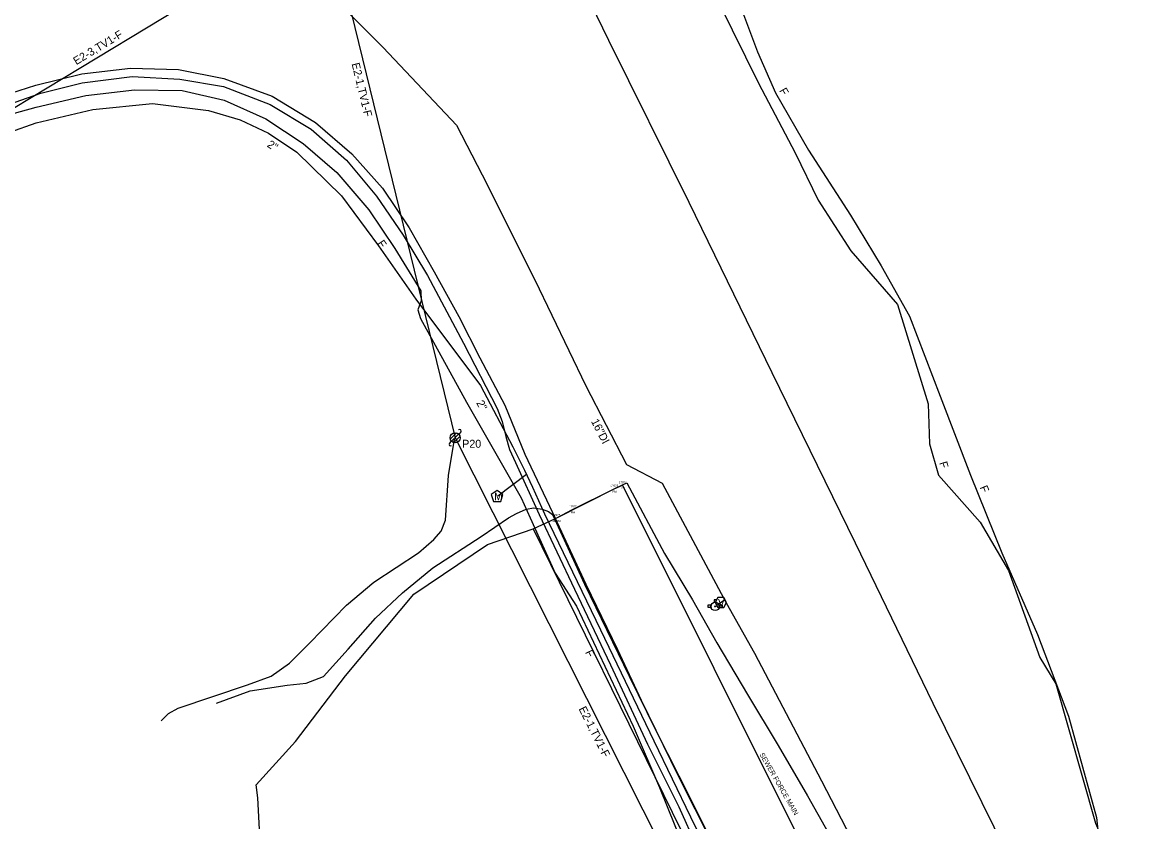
# Model space of a CAD drawing. Extents: x 1614474 to 1865144, y 1098877 to 1212550.
# Drawn here: x 1755283 to 1755840, y 1168586 to 1168985 of the extents above; entities that cross this region are included whole.
import ezdxf

# ---------------------------------------------------------------- set-up
doc = ezdxf.new("R2010")
doc.units = 0
for name, color, linetype in [('RD_EX_SU_Elec', 7, 'Continuous'), ('RD_EX_SU_H2O', 7, 'Continuous'), ('RD_EX_SU_Ovhd', 7, 'Continuous'), ('RD_EX_SU_Pole', 7, 'Continuous'), ('RD_EX_SU_Sewer', 7, 'Continuous'), ('RD_EX_SU_Telecom', 7, 'Continuous'), ('RD_EX_SU_TX_H2O', 7, 'Continuous'), ('RD_EX_SU_TX_Pole', 7, 'Continuous'), ('RD_EX_SU_TX_Sewer', 7, 'Continuous'), ('RD_EX_SU_TX_Telecom', 7, 'Continuous'), ('RD_EX_VEG_txCode', 7, 'Continuous'), ('RD_SMD_Locator', 7, 'Continuous')]:
    doc.layers.add(name, color=color, linetype=linetype)

msp = doc.modelspace()

# ---------------------------------------------------------------- linework, layer by layer
at = {"layer": 'RD_EX_SU_Elec'}
msp.add_lwpolyline([(1755352.15, 1168636.03), (1755355.71, 1168639.76), (1755360.62, 1168642.49), (1755377.96, 1168648.25), (1755395.32, 1168654.04), (1755407.08, 1168658.47), (1755416.27, 1168664.85), (1755426.19, 1168674.91), (1755444.85, 1168693.91), (1755458.49, 1168705.44), (1755480.84, 1168720.11), (1755488.48, 1168726.7), (1755492.01, 1168730.8), (1755494.34, 1168736.34), (1755495.74, 1168758.73), (1755498.75, 1168776.84)], dxfattribs=at)
at = {"layer": 'RD_EX_SU_H2O'}
for p, q in [((1755520.4, 1168748.47), (1755534.69, 1168759.32)), ((1755628.57, 1168696.63), (1755628.57, 1168695.3)), ((1755629.62, 1168696.63), (1755628.57, 1168696.63)), ((1755629.62, 1168695.27), (1755629.62, 1168696.63)), ((1755629.84, 1168693.84), (1755633.69, 1168696.62)), ((1755627.04, 1168693.86), (1755625.4, 1168693.86)), ((1755625.4, 1168693.86), (1755625.4, 1168692.81)), ((1755625.4, 1168692.81), (1755627, 1168692.81)), ((1755632.75, 1168693.86), (1755631.06, 1168693.86)), ((1755631.1, 1168692.81), (1755632.75, 1168692.81)), ((1755632.75, 1168692.81), (1755632.75, 1168693.86))]:
    msp.add_line(p, q, dxfattribs=at)
for points in [[(1755385.42, 1169098.44), (1755401.32, 1169066.46), (1755415.89, 1169036.4), (1755422.95, 1169020.76), (1755426.26, 1169009.34), (1755463.14, 1168972.48), (1755499.82, 1168933.69), (1755512.6, 1168909), (1755538.91, 1168856.4), (1755564.45, 1168803.54), (1755584.77, 1168764.26), (1755602.59, 1168754.78), (1755634.52, 1168695.09), (1755648.65, 1168669.94), (1755682.22, 1168606.15), (1755709.26, 1168554.06), (1755726.87, 1168521.3)], [(1755263.17, 1168925.56), (1755289.7, 1168934.96), (1755317.93, 1168941.55), (1755347.73, 1168944.49), (1755375.7, 1168941.09), (1755391.63, 1168936.36), (1755405.8, 1168929.69), (1755420, 1168920.26), (1755442.22, 1168898.37), (1755460.76, 1168873.49), (1755479.47, 1168846.77), (1755511.72, 1168803.69), (1755527.96, 1168773), (1755533.67, 1168761.43), (1755537.79, 1168752.87), (1755543.72, 1168739.55), (1755571.82, 1168681.62), (1755598.4, 1168626.16), (1755616.79, 1168588.07), (1755634.63, 1168551.68)]]:
    msp.add_lwpolyline(points, dxfattribs=at)
for points in [[(1755520.04, 1168751.27), (1755517.14, 1168749.16), (1755518.25, 1168745.75), (1755521.84, 1168745.75), (1755522.94, 1168749.16)], [(1755634.81, 1168695.15), (1755633.37, 1168697.65), (1755630.48, 1168697.65), (1755629.04, 1168695.15), (1755630.48, 1168692.65), (1755633.37, 1168692.65)]]:
    msp.add_lwpolyline(points, close=True, dxfattribs=at)
for radius in [2.1, 0.263]:
    msp.add_circle((1755629.05, 1168693.25), radius, dxfattribs=at)
for start, end in [(163.3387, 192.315), (74.2455, 103.2128), (347.685, 16.6613)]:
    msp.add_arc((1755629.05, 1168693.25), 2.1, start, end, dxfattribs=at)
at = {"layer": 'RD_EX_SU_Ovhd'}
for p, q in [((1755252.17, 1168926.49), (1755435.58, 1169037.63)), ((1755435.58, 1169037.63), (1755499.08, 1168777.54)), ((1755499.08, 1168777.54), (1755611.8, 1168554.19))]:
    msp.add_line(p, q, dxfattribs=at)
at = {"layer": 'RD_EX_SU_Pole'}
for p, q in [((1755496.66, 1168776.89), (1755499.72, 1168779.95)), ((1755497.31, 1168775.77), (1755500.84, 1168779.31)), ((1755500.84, 1168779.31), (1755501.9, 1168780.37)), ((1755496.25, 1168774.71), (1755497.31, 1168775.77)), ((1755498.43, 1168775.13), (1755501.49, 1168778.19))]:
    msp.add_line(p, q, dxfattribs=at)
msp.add_circle((1755499.08, 1168777.54), 2.5, dxfattribs=at)
for centre, start, end in [((1755501.37, 1168780.9), 315, 135), ((1755496.78, 1168774.18), 135, 315)]:
    msp.add_arc(centre, 0.75, start, end, dxfattribs=at)
at = {"layer": 'RD_EX_SU_Sewer'}
for points in [[(1755401.74, 1168572.3), (1755400.52, 1168597.56), (1755399.65, 1168604.04), (1755419.32, 1168625.72), (1755444.21, 1168658.58), (1755478.45, 1168699.38), (1755515.21, 1168724.24), (1755538.02, 1168731.98), (1755549.18, 1168737.18), (1755579.59, 1168752.57), (1755584.91, 1168755.1), (1755603.82, 1168719.72), (1755617.74, 1168696.64), (1755629.86, 1168675.11), (1755645.29, 1168649.26), (1755660.6, 1168623.75), (1755675.18, 1168598.54), (1755689.17, 1168573.75)], [(1755538.02, 1168731.98), (1755677.08, 1168448.83)]]:
    msp.add_lwpolyline(points, dxfattribs=at)
at = {"layer": 'RD_EX_SU_Telecom'}
for points in [[(1755590.16, 1169126.29), (1755590.98, 1169107.71), (1755588.59, 1169093.98), (1755585.74, 1169086.47), (1755598.29, 1169061.2), (1755650.69, 1168954.78), (1755669.04, 1168919.98), (1755680.52, 1168896.3), (1755696.94, 1168870.9), (1755720.15, 1168844.14), (1755735.51, 1168794.5), (1755736.19, 1168774.57), (1755740.79, 1168758.88), (1755761.5, 1168735.33), (1755775.66, 1168711.24), (1755791.36, 1168667.81), (1755799.39, 1168654.61), (1755819.15, 1168584.91), (1755822.92, 1168576.29), (1755830.76, 1168551.82), (1755839.8, 1168530.61)], [(1755515.3, 1169100.63), (1755575.8, 1168976.27), (1755615.82, 1168895.28), (1755657.46, 1168810.23), (1755699.13, 1168725.09), (1755737.87, 1168644.92), (1755774.46, 1168570.64)], [(1755643.16, 1168988.99), (1755650.24, 1168970.42), (1755659.27, 1168949.97), (1755675.7, 1168921.3), (1755696.74, 1168888.73), (1755711.98, 1168863.4), (1755726.14, 1168838.3), (1755741.49, 1168798.28), (1755756.63, 1168758.91), (1755772.29, 1168720.09), (1755790.19, 1168679.27), (1755805.71, 1168638.46), (1755819.76, 1168587.82), (1755820.42, 1168581.52)], [(1755268.41, 1168947.14), (1755289.41, 1168953.77), (1755312.39, 1168959.32), (1755336.84, 1168962.31), (1755360.73, 1168961.58), (1755383.48, 1168957.08), (1755407.65, 1168948.23), (1755429.34, 1168935), (1755447.51, 1168919.47), (1755462.71, 1168902.2), (1755476.06, 1168882.48), (1755488.57, 1168860.52), (1755500.87, 1168838.21), (1755511.35, 1168817.55), (1755523.89, 1168793.88), (1755533.94, 1168769.38), (1755547.81, 1168740.19), (1755564.48, 1168704.4), (1755580.18, 1168671.75), (1755592.08, 1168646.44), (1755610.47, 1168608.91), (1755627.34, 1168575.22)], [(1755272.39, 1168942.94), (1755291.95, 1168949.71), (1755312.56, 1168954.88), (1755337.65, 1168958.12), (1755361.46, 1168956.8), (1755383.25, 1168953.03), (1755406.57, 1168944.08), (1755427.09, 1168931.76), (1755444.74, 1168916.29), (1755459.8, 1168898.32), (1755473.09, 1168878.8), (1755485.28, 1168858.56), (1755503.24, 1168824.79), (1755520.07, 1168792.15), (1755522.53, 1168785.59), (1755524.49, 1168778.11), (1755526.21, 1168771.73), (1755529.29, 1168765.17), (1755541.09, 1168739.22), (1755558.67, 1168701.88), (1755576.72, 1168664.11), (1755595.28, 1168624.37), (1755610.86, 1168593.19), (1755619.66, 1168573.4)], [(1755253.36, 1168932.67), (1755289.59, 1168942.81), (1755314.38, 1168948.53), (1755338.86, 1168951.41), (1755362.56, 1168951.04), (1755383.58, 1168946.19), (1755404.43, 1168936.99), (1755423.08, 1168924.59), (1755439.99, 1168910.02), (1755455.99, 1168891.45), (1755468.93, 1168872.09), (1755481.86, 1168850.91), (1755482.08, 1168845.94), (1755480.47, 1168841.41), (1755481.82, 1168837.2), (1755504.75, 1168795.3), (1755532.15, 1168747.5), (1755536.58, 1168737.5), (1755549.01, 1168709.89), (1755559.7, 1168693.42), (1755588.06, 1168633.45), (1755601.28, 1168602.82), (1755616.31, 1168565.61)], [(1755512.1, 1168728.24), (1755525.71, 1168737.52), (1755529.7, 1168739.68), (1755534.51, 1168741.84), (1755538.4, 1168742.46), (1755542.64, 1168741.85), (1755545.72, 1168740.78), (1755547.74, 1168739.27), (1755552.53, 1168728.77), (1755563.81, 1168704.31), (1755586.05, 1168658.34), (1755599.42, 1168631.31), (1755616.67, 1168597.14), (1755633.05, 1168564.37), (1755647.91, 1168532.61), (1755657.47, 1168510.73), (1755668.47, 1168487.78), (1755675.2, 1168471.07), (1755685.09, 1168450.55), (1755686.31, 1168447), (1755686.46, 1168443.88), (1755687.07, 1168433.57), (1755682.96, 1168431.41)], [(1755379.76, 1168644.85), (1755396.66, 1168651.06), (1755415.05, 1168653.92), (1755424.6, 1168654.88), (1755433.24, 1168658.21), (1755445.63, 1168671.96), (1755459.2, 1168687.37), (1755472.73, 1168700.1), (1755487.98, 1168712.53), (1755512.1, 1168728.24)]]:
    msp.add_lwpolyline(points, dxfattribs=at)
at = {"layer": 'RD_EX_SU_TX_Sewer'}
msp.add_lwpolyline([(1755549.64, 1168737.44), (1755557.76, 1168741.71), (1755578.58, 1168752.1), (1755582.79, 1168753.78), (1755719.92, 1168479.2), (1755747.6, 1168492), (1755775.92, 1168507.94), (1755800.38, 1168518.87), (1755831.36, 1168520.25)], dxfattribs=at)
at = {"layer": 'RD_SMD_Locator'}
for centre in [(1755578.58, 1168752.1), (1755582.79, 1168753.78), (1755557.76, 1168741.71), (1755549.64, 1168737.44)]:
    msp.add_circle(centre, 0.001, dxfattribs=at)

# ---------------------------------------------------------------- texts
at = {"layer": 'RD_EX_SU_H2O'}
for s, p in [('M', (1755518.61, 1168746.35)), ('V', (1755630.49, 1168693.28))]:
    msp.add_text(s, height=3.75, dxfattribs=at).set_placement(p)
at = {"layer": 'RD_EX_SU_Ovhd'}
for s, rotation, p in [('E2-3,TV1-F', 31.214, (1755309.69, 1168963.68)), ('E2-1,TV1-F', 283.7195, (1755447.28, 1168964.42)), ('E2-1,TV1-F', 296.7794, (1755560.72, 1168642.09))]:
    msp.add_text(s, height=4, rotation=rotation, dxfattribs=at).set_placement(p)
at = {"layer": 'RD_EX_SU_TX_H2O'}
for s, rotation, p in [('2"', 326.3944, (1755404.74, 1168923.2)), ('2"', 297.8865, (1755509.51, 1168795.04)), ('16"DI', 297.3571, (1755566.89, 1168785.77))]:
    msp.add_text(s, height=4, rotation=rotation, dxfattribs=at).set_placement(p)
at = {"layer": 'RD_EX_SU_TX_Pole'}
msp.add_text('P20', height=4, dxfattribs=at).set_placement((1755502.6, 1168772.54))
at = {"layer": 'RD_EX_SU_TX_Sewer'}
msp.add_text('SEWER FORCE MAIN', height=2.5, rotation=299.8247, dxfattribs=at).set_placement((1755651.15, 1168619.27))
at = {"layer": 'RD_EX_SU_TX_Telecom'}
for rotation, p in [(299.8264, (1755660.97, 1168951.01)), (303.7459, (1755459.98, 1168874.68)), (286.354, (1755741.06, 1168765.06)), (291.963, (1755761.26, 1168752.78)), (295.3092, (1755563.95, 1168670.39))]:
    msp.add_text('F', height=4, rotation=rotation, dxfattribs=at).set_placement(p)
at = {"layer": 'RD_EX_VEG_txCode'}
for s, p in [('17078', (1755576.74, 1168753.1)), ('17079', (1755580.95, 1168754.78)), ('FM', (1755581.97, 1168751.78)), ('FM', (1755577.76, 1168750.1)), ('17077', (1755555.93, 1168742.71)), ('FM', (1755556.94, 1168739.71)), ('BL*FM', (1755547.49, 1168735.44)), ('17076', (1755547.78, 1168738.44))]:
    msp.add_text(s, height=1, dxfattribs=at).set_placement(p)

doc.saveas('drawing.dxf')
